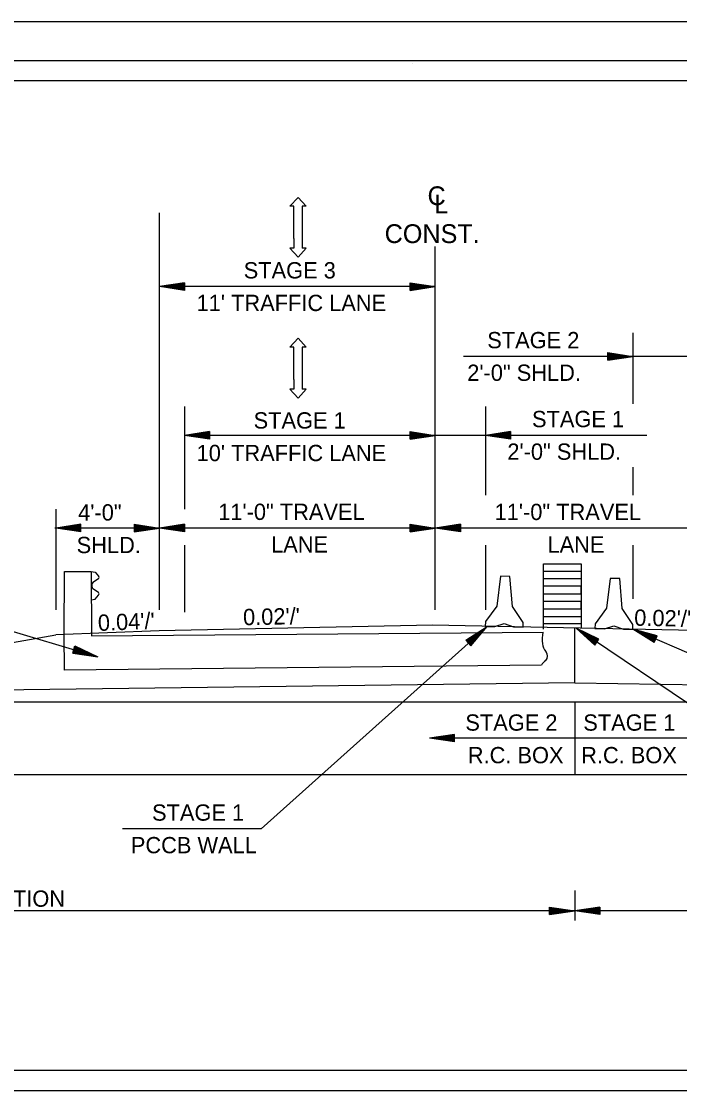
# Model space of a CAD drawing. Extents: x 1368648 to 1927880, y -1037443 to 380209.
# Drawn here: x 1372375 to 1372703, y 379220 to 379753 of the extents above; entities that cross this region are included whole.
import ezdxf

# ---------------------------------------------------------------- set-up
doc = ezdxf.new("R2010")
doc.units = 0
for name, color, linetype in [('CL Construction', 7, 'Continuous'), ('Default', 7, 'Continuous'), ('Dimensions', 7, 'Continuous'), ('Level 1', 7, 'Continuous'), ('R_Border', 7, 'Continuous'), ('R_Border Plan-Plan', 7, 'Continuous'), ('R_Dimension', 7, 'Continuous'), ('R_Fin Surface', 7, 'Continuous'), ('R_MOT', 7, 'Continuous'), ('R_No Plot', 7, 'Continuous')]:
    doc.layers.add(name, color=color, linetype=linetype)

msp = doc.modelspace()

# ---------------------------------------------------------------- linework, layer by layer
at = {"layer": 'CL Construction'}
msp.add_line((1372581.24, 379459.31), (1372581.24, 379640.51), dxfattribs=at)
at = {"layer": 'Default'}
for p, q in [((1372396.38, 379446.98), (1372396.4, 379478.45)), ((1372396.4, 379478.45), (1372409.73, 379478.45)), ((1372409.73, 379478.45), (1372411.74, 379478.04)), ((1372409.73, 379478.45), (1372409.88, 379446.28)), ((1372411.74, 379478.04), (1372413.38, 379476.18)), ((1372635.09, 379482.3), (1372653.84, 379482.3)), ((1372635.09, 379449.69), (1372635.09, 379482.3)), ((1372635.09, 379478.55), (1372653.84, 379478.55)), ((1372635.09, 379474.8), (1372635.09, 379478.55)), ((1372653.84, 379482.3), (1372653.84, 379450.15)), ((1372413.38, 379474.75), (1372410.58, 379472.93)), ((1372653.84, 379474.8), (1372635.09, 379474.8)), ((1372410.16, 379471.74), (1372410.16, 379471.02)), ((1372413.38, 379468), (1372410.58, 379469.83)), ((1372411.74, 379464.72), (1372413.38, 379466.58)), ((1372653.84, 379471.05), (1372635.09, 379471.05)), ((1372635.09, 379467.3), (1372653.84, 379467.3)), ((1372653.84, 379467.3), (1372653.84, 379471.05)), ((1372409.73, 379464.31), (1372411.74, 379464.72)), ((1372653.84, 379463.55), (1372635.09, 379463.55)), ((1372653.84, 379459.8), (1372653.84, 379463.55)), ((1372635.09, 379459.8), (1372653.84, 379459.8)), ((1372635.09, 379456.05), (1372653.84, 379456.05)), ((1372635.09, 379452.3), (1372635.09, 379456.05)), ((1372653.84, 379452.3), (1372635.09, 379452.3)), ((1372396.43, 379429.23), (1372396.38, 379446.98)), ((1372409.88, 379446.28), (1372634.89, 379448.12)), ((1372650.7, 379422.95), (1372650.7, 379450.21)), ((1372634.08, 379431.81), (1372396.43, 379429.23)), ((1372650.7, 379422.95), (1372221.66, 379417.35)), ((1372650.7, 379422.95), (1372945.4, 379418.15)), ((1372199.05, 379413.45), (1372954.18, 379413.51)), ((1372650.7, 379413.48), (1372650.7, 379377.14)), ((1372135.15, 379377.14), (1373018.09, 379377.14))]:
    msp.add_line(p, q, dxfattribs=at)
for centre, radius, start, end in [((1372411.62, 379471.89), 1.47, 135.1949, 185.8556), ((1372412.79, 379475.47), 0.925, 309.5141, 50.4859), ((1372411.62, 379470.87), 1.47, 174.1444, 224.8051), ((1372412.79, 379467.29), 0.925, 309.5141, 50.4859), ((1372653.4, 379444.37), 18.89, 168.525, 185.9092), ((1372641.64, 379443.1), 7.06, 185.5456, 220.8363), ((1372633.87, 379436.27), 3.29, 318.0243, 42.2537), ((1372639.96, 379428.22), 6.89, 121.9577, 148.6088)]:
    msp.add_arc(centre, radius, start, end, dxfattribs=at)
at = {"layer": 'Dimensions'}
for p, q in [((1372514.86, 379660.52), (1372514.86, 379639.63)), ((1372514.86, 379590.24), (1372514.86, 379569.35))]:
    msp.add_line(p, q, dxfattribs=at)
for points in [[(1372510.8, 379644.51), (1372510.8, 379660.52), (1372508.77, 379660.52), (1372512.83, 379664.98), (1372516.89, 379660.52), (1372514.86, 379660.52)], [(1372510.8, 379644.51), (1372510.8, 379639.63), (1372508.77, 379639.63), (1372512.83, 379635.18), (1372516.89, 379639.63), (1372514.86, 379639.63)], [(1372510.8, 379574.23), (1372510.8, 379590.24), (1372508.77, 379590.24), (1372512.83, 379594.7), (1372516.89, 379590.24), (1372514.86, 379590.24)], [(1372510.8, 379574.23), (1372510.8, 379569.35), (1372508.77, 379569.35), (1372512.83, 379564.9), (1372516.89, 379569.35), (1372514.86, 379569.35)]]:
    msp.add_lwpolyline(points, dxfattribs=at)
at = {"layer": 'Level 1'}
for p, q in [((1372613.71, 379476.07), (1372611.85, 379461.18)), ((1372618.42, 379475.98), (1372613.71, 379476.07)), ((1372619.7, 379461.03), (1372618.42, 379475.98)), ((1372668.37, 379475), (1372666.51, 379460.11)), ((1372673.09, 379474.91), (1372668.37, 379475)), ((1372674.36, 379459.96), (1372673.09, 379474.91)), ((1372611.85, 379461.18), (1372606.2, 379453.44)), ((1372625.04, 379453.07), (1372619.7, 379461.03)), ((1372666.51, 379460.11), (1372660.86, 379452.37)), ((1372679.71, 379452), (1372674.36, 379459.96)), ((1372606.2, 379453.44), (1372606.13, 379451.09)), ((1372606.13, 379451.09), (1372610.84, 379450.99)), ((1372610.84, 379450.99), (1372615.58, 379452.47)), ((1372615.58, 379452.47), (1372620.26, 379450.81)), ((1372620.26, 379450.81), (1372624.97, 379450.72)), ((1372624.97, 379450.72), (1372625.04, 379453.07)), ((1372660.86, 379452.37), (1372660.79, 379450.01)), ((1372665.5, 379449.92), (1372670.24, 379451.4)), ((1372670.24, 379451.4), (1372674.92, 379449.74)), ((1372679.63, 379449.64), (1372679.71, 379452)), ((1372660.79, 379450.01), (1372665.5, 379449.92)), ((1372674.92, 379449.74), (1372679.63, 379449.64))]:
    msp.add_line(p, q, dxfattribs=at)
at = {"layer": 'R_Border'}
for p, q in [((1371807.4, 379733.26), (1373388.3, 379733.26)), ((1372570, 379731.96), (1372570, 379731.96)), ((1372570, 379731.96), (1372570, 379731.96))]:
    msp.add_line(p, q, dxfattribs=at)
at = {"layer": 'R_Border Plan-Plan'}
msp.add_line((1371807.4, 379219.61), (1373388.3, 379219.61), dxfattribs=at)
at = {"layer": 'R_Dimension'}
for p, q in [((1372443.74, 379568.93), (1372443.74, 379657.34)), ((1372456.24, 379622.34), (1372443.74, 379620.47)), ((1372456.24, 379622.03), (1372445.82, 379620.47)), ((1372456.24, 379621.71), (1372447.97, 379620.47)), ((1372456.24, 379621.4), (1372450.05, 379620.47)), ((1372456.24, 379622.34), (1372456.24, 379618.59)), ((1372568.71, 379622.34), (1372581.21, 379620.47)), ((1372568.71, 379618.59), (1372568.71, 379622.34)), ((1372568.71, 379622.03), (1372579.12, 379620.47)), ((1372568.71, 379621.71), (1372576.97, 379620.47)), ((1372568.71, 379621.4), (1372574.89, 379620.47)), ((1372581.21, 379620.47), (1372443.74, 379620.47)), ((1372456.24, 379618.59), (1372443.74, 379620.47)), ((1372456.24, 379618.9), (1372445.82, 379620.47)), ((1372456.24, 379619.22), (1372447.97, 379620.47)), ((1372456.24, 379619.53), (1372450.05, 379620.47)), ((1372456.24, 379621.07), (1372452.17, 379620.47)), ((1372456.24, 379619.85), (1372452.17, 379620.47)), ((1372456.24, 379620.76), (1372454.26, 379620.47)), ((1372456.24, 379620.17), (1372454.26, 379620.47)), ((1372568.71, 379621.08), (1372572.77, 379620.47)), ((1372568.71, 379620.76), (1372570.69, 379620.47)), ((1372568.71, 379618.59), (1372581.21, 379620.47)), ((1372568.71, 379619.86), (1372572.77, 379620.47)), ((1372568.71, 379619.22), (1372576.97, 379620.47)), ((1372568.71, 379618.9), (1372579.12, 379620.47)), ((1372568.71, 379619.53), (1372574.89, 379620.47)), ((1372568.71, 379620.17), (1372570.69, 379620.47)), ((1372679.61, 379597.36), (1372679.61, 379562.04)), ((1372842.21, 379585.69), (1372595.2, 379585.69)), ((1372667.11, 379587.57), (1372679.61, 379585.69)), ((1372667.11, 379583.82), (1372667.11, 379587.57)), ((1372667.11, 379587.25), (1372677.52, 379585.69)), ((1372667.11, 379586.94), (1372675.37, 379585.69)), ((1372667.11, 379586.62), (1372673.29, 379585.69)), ((1372667.11, 379586.3), (1372671.17, 379585.69)), ((1372667.11, 379585.99), (1372669.09, 379585.69)), ((1372667.11, 379583.82), (1372679.61, 379585.69)), ((1372667.11, 379585.09), (1372671.17, 379585.69)), ((1372667.11, 379584.45), (1372675.37, 379585.69)), ((1372667.11, 379584.13), (1372677.52, 379585.69)), ((1372667.11, 379584.76), (1372673.29, 379585.69)), ((1372667.11, 379585.4), (1372669.09, 379585.69)), ((1372443.74, 379459.31), (1372443.74, 379568.93)), ((1372456.26, 379560.64), (1372456.26, 379517.95)), ((1372606.24, 379560.64), (1372606.24, 379516.47)), ((1372468.76, 379548.21), (1372456.26, 379546.33)), ((1372468.76, 379547.89), (1372458.35, 379546.33)), ((1372468.76, 379547.58), (1372460.5, 379546.33)), ((1372468.76, 379547.26), (1372462.58, 379546.33)), ((1372468.76, 379546.94), (1372464.7, 379546.33)), ((1372468.76, 379546.63), (1372466.79, 379546.33)), ((1372468.76, 379548.21), (1372468.76, 379544.46)), ((1372568.71, 379548.21), (1372581.21, 379546.33)), ((1372568.71, 379544.46), (1372568.71, 379548.21)), ((1372568.71, 379547.89), (1372579.12, 379546.33)), ((1372568.71, 379547.58), (1372576.97, 379546.33)), ((1372568.71, 379547.26), (1372574.89, 379546.33)), ((1372568.71, 379546.94), (1372572.77, 379546.33)), ((1372568.71, 379546.63), (1372570.69, 379546.33)), ((1372618.74, 379548.21), (1372606.24, 379546.33)), ((1372618.74, 379547.89), (1372608.32, 379546.33)), ((1372618.74, 379547.58), (1372610.47, 379546.33)), ((1372618.74, 379547.26), (1372612.55, 379546.33)), ((1372618.74, 379546.94), (1372614.67, 379546.33)), ((1372618.74, 379546.63), (1372616.76, 379546.33)), ((1372618.74, 379548.21), (1372618.74, 379544.46)), ((1372686.69, 379546.33), (1372456.26, 379546.33)), ((1372468.76, 379544.46), (1372456.26, 379546.33)), ((1372468.76, 379544.77), (1372458.35, 379546.33)), ((1372468.76, 379545.09), (1372460.5, 379546.33)), ((1372468.76, 379545.4), (1372462.58, 379546.33)), ((1372468.76, 379545.72), (1372464.7, 379546.33)), ((1372468.76, 379546.04), (1372466.79, 379546.33)), ((1372568.71, 379544.46), (1372581.21, 379546.33)), ((1372568.71, 379545.73), (1372572.77, 379546.33)), ((1372568.71, 379545.09), (1372576.97, 379546.33)), ((1372568.71, 379544.77), (1372579.12, 379546.33)), ((1372568.71, 379545.4), (1372574.89, 379546.33)), ((1372568.71, 379546.04), (1372570.69, 379546.33)), ((1372618.74, 379544.46), (1372606.24, 379546.33)), ((1372618.74, 379544.77), (1372608.32, 379546.33)), ((1372618.74, 379545.09), (1372610.47, 379546.33)), ((1372618.74, 379545.4), (1372612.55, 379546.33)), ((1372618.74, 379545.72), (1372614.67, 379546.33)), ((1372618.74, 379546.04), (1372616.76, 379546.33)), ((1372679.61, 379530.51), (1372679.61, 379516.47)), ((1372456.26, 379517.95), (1372456.26, 379509.53)), ((1372392.16, 379509.53), (1372392.16, 379467.59)), ((1372443.74, 379500.08), (1372391.66, 379500.08)), ((1372404.66, 379501.96), (1372392.16, 379500.08)), ((1372404.66, 379498.21), (1372392.16, 379500.08)), ((1372404.66, 379501.64), (1372394.25, 379500.08)), ((1372404.66, 379498.52), (1372394.25, 379500.08)), ((1372404.66, 379501.33), (1372396.4, 379500.08)), ((1372404.66, 379498.84), (1372396.4, 379500.08)), ((1372404.66, 379501.01), (1372398.48, 379500.08)), ((1372404.66, 379499.15), (1372398.48, 379500.08)), ((1372404.66, 379500.69), (1372400.6, 379500.08)), ((1372404.66, 379499.48), (1372400.6, 379500.08)), ((1372404.66, 379500.38), (1372402.69, 379500.08)), ((1372404.66, 379499.79), (1372402.69, 379500.08)), ((1372404.66, 379498.21), (1372404.66, 379501.96)), ((1372431.24, 379501.96), (1372443.74, 379500.08)), ((1372431.24, 379501.96), (1372431.24, 379498.21)), ((1372431.24, 379501.64), (1372441.65, 379500.08)), ((1372431.24, 379501.33), (1372439.5, 379500.08)), ((1372431.24, 379501.01), (1372437.42, 379500.08)), ((1372431.24, 379500.69), (1372435.3, 379500.08)), ((1372431.24, 379500.38), (1372433.21, 379500.08)), ((1372431.24, 379498.21), (1372443.74, 379500.08)), ((1372431.24, 379499.47), (1372435.3, 379500.08)), ((1372431.24, 379498.84), (1372439.5, 379500.08)), ((1372431.24, 379498.52), (1372441.65, 379500.08)), ((1372431.24, 379499.15), (1372437.42, 379500.08)), ((1372431.24, 379499.79), (1372433.21, 379500.08)), ((1372456.24, 379501.96), (1372443.74, 379500.08)), ((1372581.21, 379500.08), (1372443.74, 379500.08)), ((1372456.24, 379498.21), (1372443.74, 379500.08)), ((1372456.24, 379501.64), (1372445.82, 379500.08)), ((1372456.24, 379498.52), (1372445.82, 379500.08)), ((1372456.24, 379501.33), (1372447.97, 379500.08)), ((1372456.24, 379498.84), (1372447.97, 379500.08)), ((1372456.24, 379501.01), (1372450.05, 379500.08)), ((1372456.24, 379499.15), (1372450.05, 379500.08)), ((1372456.24, 379500.69), (1372452.17, 379500.08)), ((1372456.24, 379499.47), (1372452.17, 379500.08)), ((1372456.24, 379500.38), (1372454.26, 379500.08)), ((1372456.24, 379499.79), (1372454.26, 379500.08)), ((1372456.24, 379501.96), (1372456.24, 379498.21)), ((1372568.71, 379501.96), (1372581.21, 379500.08)), ((1372568.71, 379498.21), (1372568.71, 379501.96)), ((1372568.71, 379501.64), (1372579.12, 379500.08)), ((1372568.71, 379501.33), (1372576.97, 379500.08)), ((1372568.71, 379501.01), (1372574.89, 379500.08)), ((1372568.71, 379500.69), (1372572.77, 379500.08)), ((1372568.71, 379500.38), (1372570.69, 379500.08)), ((1372568.71, 379498.21), (1372581.21, 379500.08)), ((1372568.71, 379499.48), (1372572.77, 379500.08)), ((1372568.71, 379498.84), (1372576.97, 379500.08)), ((1372568.71, 379498.52), (1372579.12, 379500.08)), ((1372568.71, 379499.15), (1372574.89, 379500.08)), ((1372568.71, 379499.79), (1372570.69, 379500.08)), ((1372593.71, 379501.96), (1372581.21, 379500.08)), ((1372593.71, 379498.21), (1372581.21, 379500.08)), ((1372754.49, 379500.08), (1372581.24, 379500.08)), ((1372593.71, 379501.64), (1372583.3, 379500.08)), ((1372593.71, 379498.52), (1372583.3, 379500.08)), ((1372593.71, 379501.33), (1372585.45, 379500.08)), ((1372593.71, 379498.84), (1372585.45, 379500.08)), ((1372593.71, 379501.01), (1372587.53, 379500.08)), ((1372593.71, 379499.15), (1372587.53, 379500.08)), ((1372593.71, 379500.69), (1372589.65, 379500.08)), ((1372593.71, 379499.47), (1372589.65, 379500.08)), ((1372593.71, 379500.38), (1372591.74, 379500.08)), ((1372593.71, 379499.79), (1372591.74, 379500.08)), ((1372593.71, 379501.96), (1372593.71, 379498.21)), ((1372456.26, 379491.59), (1372456.26, 379463.64)), ((1372606.24, 379491.51), (1372606.24, 379459.31)), ((1372679.61, 379491.51), (1372679.61, 379464.81)), ((1372291.27, 379472.01), (1372413.1, 379435.96)), ((1372392.16, 379467.59), (1372392.16, 379459.31)), ((1372456.26, 379463.64), (1372456.26, 379458.12)), ((1372494.41, 379350.11), (1372607, 379451.07)), ((1372596.44, 379444.12), (1372607, 379451.07)), ((1372598.95, 379441.33), (1372607, 379451.07)), ((1372596.65, 379443.89), (1372605.45, 379449.67)), ((1372596.86, 379443.65), (1372603.85, 379448.24)), ((1372597.07, 379443.42), (1372602.3, 379446.85)), ((1372597.29, 379443.18), (1372600.72, 379445.44)), ((1372598.1, 379442.27), (1372600.72, 379445.44)), ((1372598.32, 379442.03), (1372602.3, 379446.85)), ((1372598.52, 379441.8), (1372603.85, 379448.24)), ((1372598.74, 379441.56), (1372605.45, 379449.67)), ((1372802.51, 379348.38), (1372651.38, 379450.2)), ((1372660.7, 379441.66), (1372651.38, 379450.2)), ((1372662.79, 379444.77), (1372651.38, 379450.2)), ((1372660.87, 379441.92), (1372653.11, 379449.03)), ((1372662.62, 379444.51), (1372653.11, 379449.03)), ((1372662.44, 379444.25), (1372654.89, 379447.83)), ((1372661.05, 379442.18), (1372654.89, 379447.83)), ((1372661.23, 379442.44), (1372656.62, 379446.67)), ((1372662.27, 379443.99), (1372656.62, 379446.67)), ((1372662.09, 379443.72), (1372658.38, 379445.48)), ((1372661.41, 379442.71), (1372658.38, 379445.48)), ((1372912.65, 379348.82), (1372679.63, 379449.64)), ((1372690.36, 379442.96), (1372679.63, 379449.64)), ((1372691.85, 379446.4), (1372679.63, 379449.64)), ((1372690.49, 379443.25), (1372681.55, 379448.82)), ((1372691.73, 379446.11), (1372681.55, 379448.82)), ((1372691.6, 379445.82), (1372683.52, 379447.96)), ((1372690.61, 379443.54), (1372683.52, 379447.96)), ((1372690.74, 379443.83), (1372685.43, 379447.14)), ((1372691.48, 379445.54), (1372685.43, 379447.14)), ((1372691.35, 379445.24), (1372687.38, 379446.29)), ((1372690.87, 379444.12), (1372687.38, 379446.29)), ((1372691.22, 379444.95), (1372689.29, 379445.47)), ((1372690.99, 379444.41), (1372689.29, 379445.47)), ((1372690.36, 379442.96), (1372691.85, 379446.4)), ((1372400.59, 379437.71), (1372401.65, 379441.3)), ((1372401.29, 379440.09), (1372405.02, 379438.35)), ((1372401.38, 379440.4), (1372407.05, 379437.75)), ((1372401.47, 379440.7), (1372409.04, 379437.16)), ((1372401.56, 379441.01), (1372411.1, 379436.55)), ((1372401.65, 379441.3), (1372413.11, 379435.96)), ((1372598.95, 379441.33), (1372596.44, 379444.12)), ((1372597.5, 379442.94), (1372599.16, 379444.04)), ((1372597.89, 379442.5), (1372599.16, 379444.04)), ((1372661.91, 379443.46), (1372660.11, 379444.32)), ((1372661.58, 379442.97), (1372660.11, 379444.32)), ((1372660.7, 379441.66), (1372662.79, 379444.77)), ((1372400.59, 379437.71), (1372413.11, 379435.96)), ((1372400.68, 379438.01), (1372411.1, 379436.55)), ((1372400.77, 379438.31), (1372409.04, 379437.16)), ((1372400.86, 379438.61), (1372407.05, 379437.75)), ((1372400.95, 379438.93), (1372405.02, 379438.35)), ((1372401.04, 379439.23), (1372403.01, 379438.95)), ((1372401.2, 379439.79), (1372403.01, 379438.95)), ((1372590.77, 379397.19), (1372578.27, 379395.31)), ((1372718.65, 379395.31), (1372578.27, 379395.31)), ((1372590.77, 379393.44), (1372578.27, 379395.31)), ((1372590.77, 379396.87), (1372580.36, 379395.31)), ((1372590.77, 379393.75), (1372580.36, 379395.31)), ((1372590.77, 379396.56), (1372582.51, 379395.31)), ((1372590.77, 379394.07), (1372582.51, 379395.31)), ((1372590.77, 379396.24), (1372584.59, 379395.31)), ((1372590.77, 379394.38), (1372584.59, 379395.31)), ((1372590.77, 379395.92), (1372586.71, 379395.31)), ((1372590.77, 379394.71), (1372586.71, 379395.31)), ((1372590.77, 379395.61), (1372588.8, 379395.31)), ((1372590.77, 379395.02), (1372588.8, 379395.31)), ((1372590.77, 379393.44), (1372590.77, 379397.19)), ((1372494.41, 379350.11), (1372425.37, 379350.11)), ((1372650.7, 379319.4), (1372650.7, 379306.93)), ((1372650.7, 379309.27), (1372085.47, 379309.27)), ((1372638.2, 379311.14), (1372650.7, 379309.27)), ((1372638.2, 379307.39), (1372638.2, 379311.14)), ((1372638.2, 379310.83), (1372648.62, 379309.27)), ((1372638.2, 379310.51), (1372646.47, 379309.27)), ((1372638.2, 379310.2), (1372644.39, 379309.27)), ((1372638.2, 379309.88), (1372642.27, 379309.27)), ((1372638.2, 379309.56), (1372640.18, 379309.27)), ((1372638.2, 379307.39), (1372650.7, 379309.27)), ((1372638.2, 379308.66), (1372642.27, 379309.27)), ((1372638.2, 379308.03), (1372646.47, 379309.27)), ((1372638.2, 379307.71), (1372648.62, 379309.27)), ((1372638.2, 379308.34), (1372644.39, 379309.27)), ((1372638.2, 379308.98), (1372640.18, 379309.27)), ((1372663.2, 379311.14), (1372650.7, 379309.27)), ((1373117.62, 379309.27), (1372650.7, 379309.27)), ((1372663.2, 379307.39), (1372650.7, 379309.27)), ((1372650.7, 379306.93), (1372650.7, 379304.47)), ((1372663.2, 379310.83), (1372652.79, 379309.27)), ((1372663.2, 379307.71), (1372652.79, 379309.27)), ((1372663.2, 379310.51), (1372654.94, 379309.27)), ((1372663.2, 379308.03), (1372654.94, 379309.27)), ((1372663.2, 379310.2), (1372657.02, 379309.27)), ((1372663.2, 379308.34), (1372657.02, 379309.27)), ((1372663.2, 379309.88), (1372659.14, 379309.27)), ((1372663.2, 379308.66), (1372659.14, 379309.27)), ((1372663.2, 379309.56), (1372661.23, 379309.27)), ((1372663.2, 379308.98), (1372661.23, 379309.27)), ((1372663.2, 379311.14), (1372663.2, 379307.39))]:
    msp.add_line(p, q, dxfattribs=at)
at = {"layer": 'R_Fin Surface'}
msp.add_line((1372199.05, 379413.45), (1372392.16, 379446.82), dxfattribs=at)
at = {"layer": 'R_MOT'}
msp.add_lwpolyline([(1372768.74, 379446.88), (1372718.71, 379448.88), (1372579.85, 379451.6), (1372443.6, 379448.83), (1372392.16, 379446.82)], dxfattribs=at)
at = {"layer": 'R_No Plot'}
for points in [[(1371745.37, 379752.73), (1373412.07, 379752.73), (1373412.07, 378686.04), (1371745.37, 378686.04)], [(1373378.3, 379229.61), (1371817.4, 379229.61), (1371817.4, 379723.26), (1373065.1, 379723.26), (1373065.1, 379673.86), (1373152.8, 379673.86), (1373273.3, 379673.86), (1373273.3, 379562.19), (1373378.3, 379562.19)], [(1371817.4, 379723.26), (1373065.1, 379723.26), (1373065.1, 379673.86), (1373152.8, 379673.86), (1373273.3, 379673.86), (1373273.3, 379562.19), (1373378.3, 379562.19), (1373378.3, 378715.96), (1371817.4, 378715.96)]]:
    msp.add_lwpolyline(points, close=True, dxfattribs=at)

# ---------------------------------------------------------------- texts
at = {"layer": 'CL Construction'}
for s, height, p in [('C', 9.37, (1372577.35, 379661.1)), ('L', 9.37, (1372580.65, 379656.98)), ('CONST.', 9.375, (1372556, 379642.19))]:
    msp.add_text(s, height=height, dxfattribs=at).set_placement(p)
at = {"layer": 'Default'}
msp.add_text("0.04'/'", height=8.125, rotation=2.2906, dxfattribs=at).set_placement((1372413.26, 379448.77))
at = {"layer": 'R_Dimension'}
for s, p in [('STAGE 3', (1372485.77, 379624.55)), ("11' TRAFFIC LANE", (1372462.29, 379608.3)), ('STAGE 2', (1372607.12, 379589.74)), ('2\'-0" SHLD.', (1372597.14, 379573.49)), ('STAGE 1', (1372490.71, 379549.71)), ('STAGE 1', (1372629.41, 379550.39)), ("10' TRAFFIC LANE", (1372462.3, 379533.46)), ('2\'-0" SHLD.', (1372617.13, 379534.14)), ('4\'-0"', (1372403.27, 379503.84)), ('11\'-0" TRAVEL', (1372473.06, 379504.14)), ('11\'-0" TRAVEL', (1372610.78, 379504.09)), ('SHLD.', (1372402.53, 379487.59)), ('LANE', (1372499.42, 379487.89)), ('LANE', (1372637.14, 379487.84)), ('STAGE 2', (1372596.21, 379399.07)), ('STAGE 1', (1372654.97, 379399.07)), ('R.C. BOX', (1372597.42, 379382.82)), ('R.C. BOX', (1372653.89, 379382.82)), ('STAGE 1', (1372440.09, 379354.19)), ('PCCB WALL', (1372429.53, 379337.94)), ('STAGE 2 CONSTRUCTION', (1372260.32, 379311.27))]:
    msp.add_text(s, height=8.125, dxfattribs=at).set_placement(p)
for rotation, p in [(1.1458, (1372485.51, 379451.63)), (358.8542, (1372680.28, 379451.42))]:
    msp.add_text("0.02'/'", height=8.125, rotation=rotation, dxfattribs=at).set_placement(p)

doc.saveas('drawing.dxf')
